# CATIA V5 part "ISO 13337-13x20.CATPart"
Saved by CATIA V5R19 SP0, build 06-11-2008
Definition: ISO 13337-13x20
Nomenclature: ISO 13337-13x20
Description: PART--DESC
Material "Steel": density 7860 kg/m3, Young's modulus 2e+11 Pa, Poisson ratio 0.266, thermal expansion 1.17e-05 1/K
Bounding box of the stored display mesh (mm): x 160.506 to 173.494, y -98 to -85.025, z 29 to 49
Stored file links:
  G:\UTB\Kombinované\Bakalářská práce\Catia\FORMA\ISO 13337-13x20.CATPart
  D:\Aplikace\CATIA\Nová složka\win_b64\startup\materials\Catalog.CATMaterial
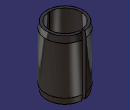
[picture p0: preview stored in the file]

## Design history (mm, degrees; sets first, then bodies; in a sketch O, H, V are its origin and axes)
Body1 "ISO 13337-13x20" (main body)
  Solid1: solid without history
